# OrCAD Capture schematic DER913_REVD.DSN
size B; title: DER-913; rev: D
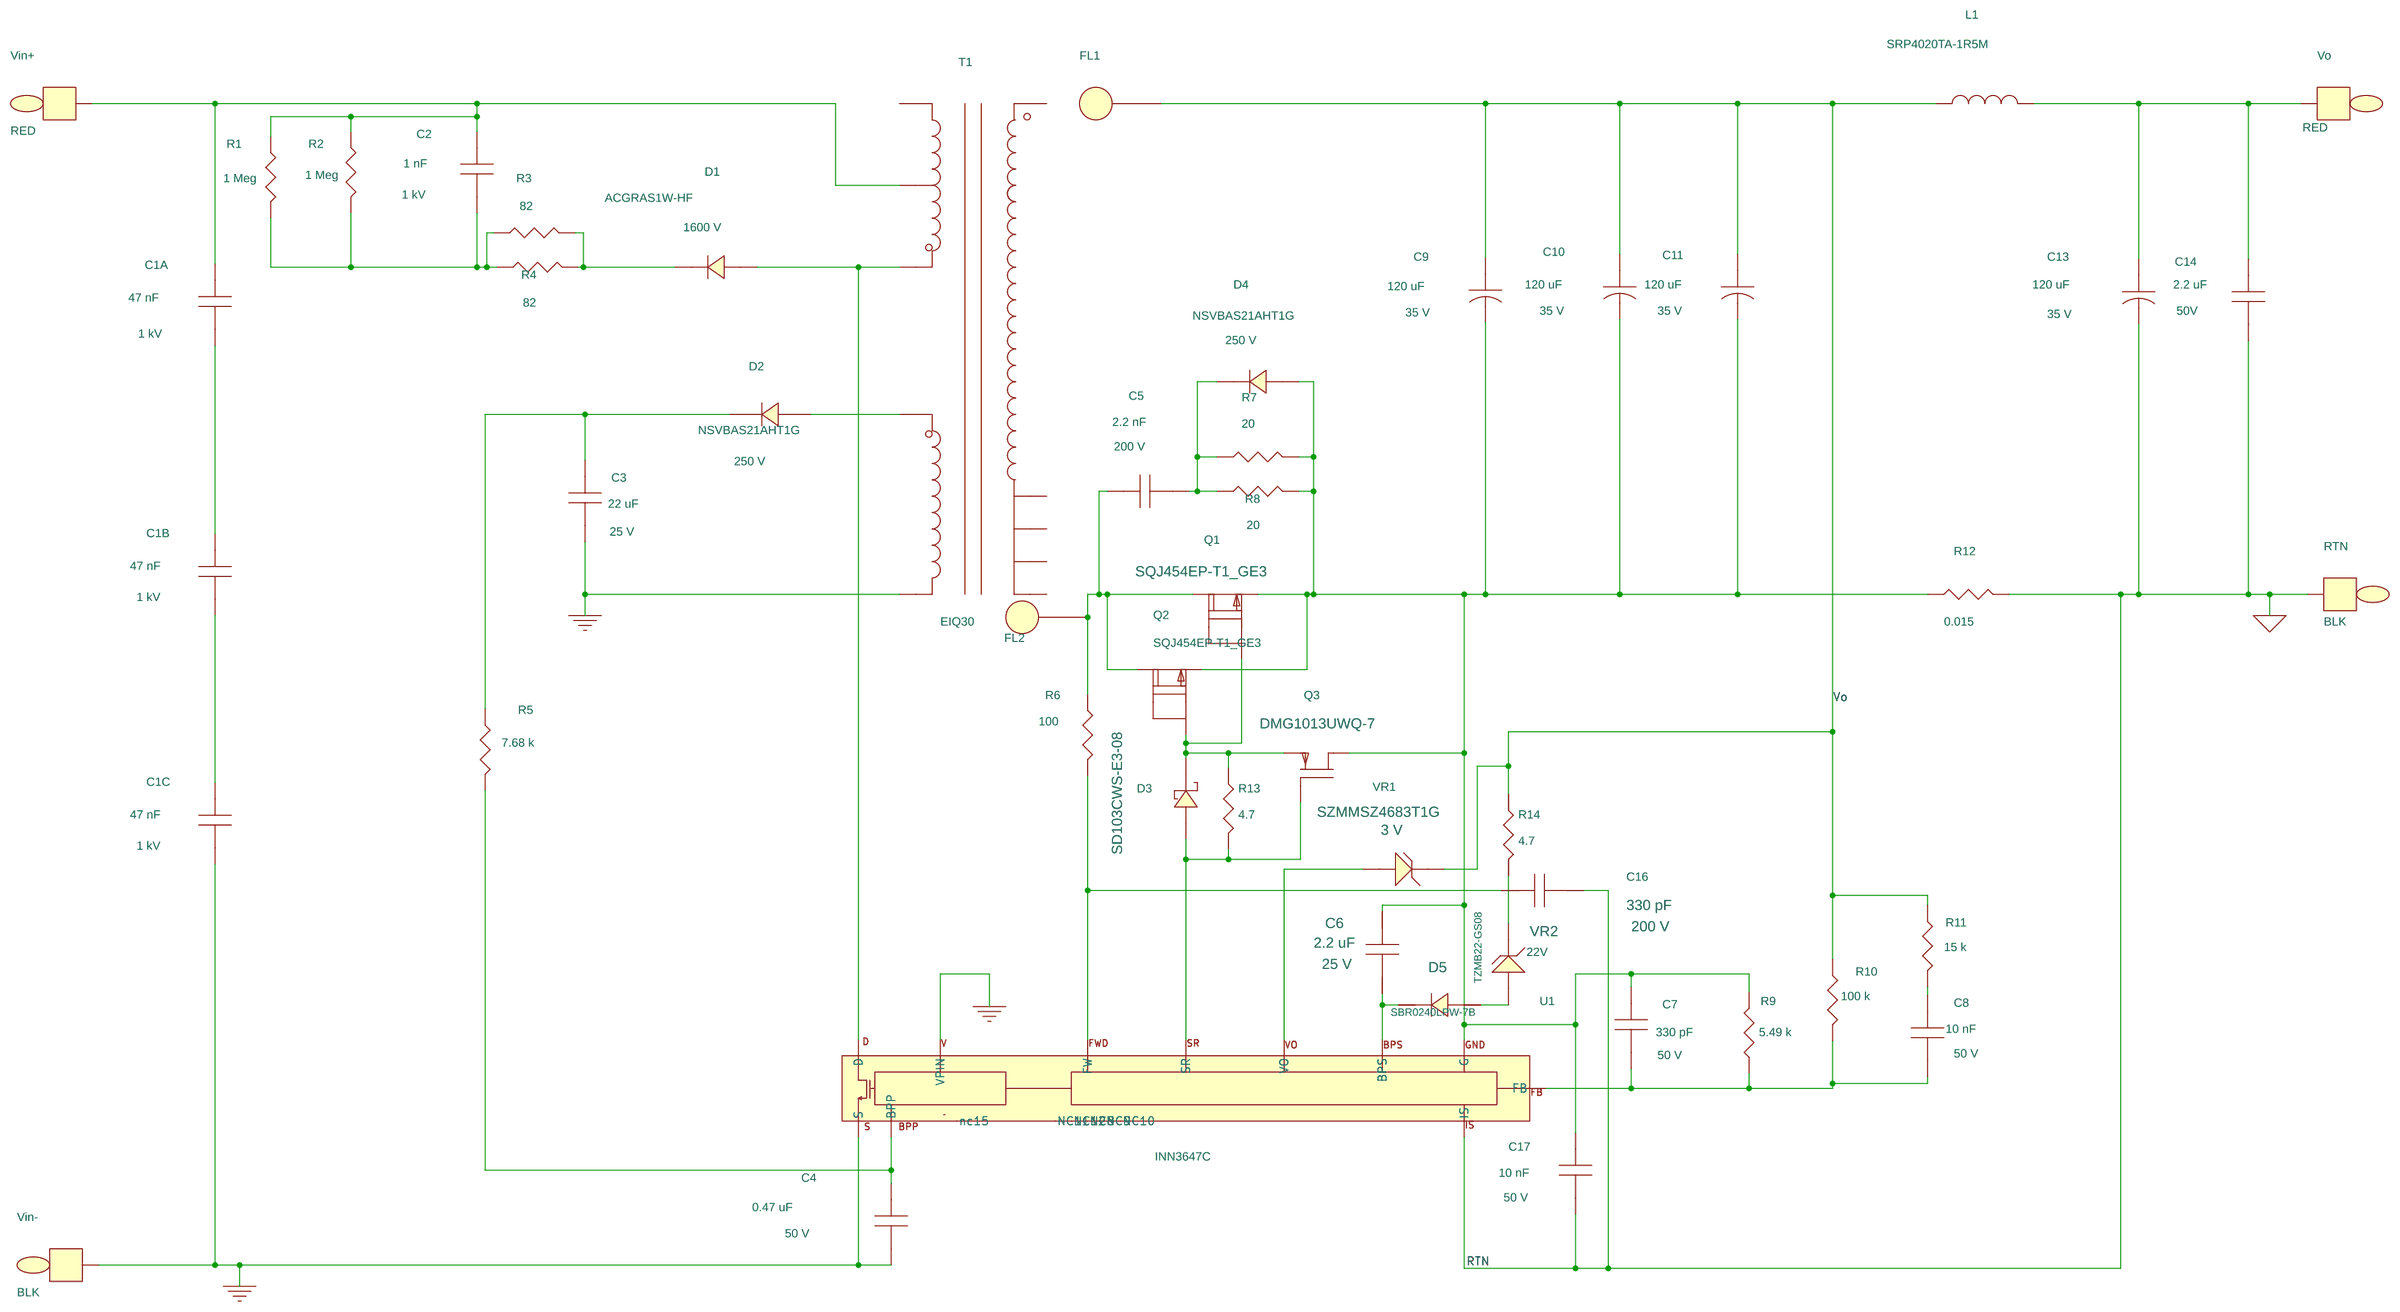
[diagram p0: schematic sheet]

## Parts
C1A  47 nF  [pismc1812]
C1B  47 nF  [pismc1812]
C1C  47 nF  [pismc1812]
C2  1 nF  [pismc1206]
C3  22 uF  [pismc0805]
C4  0.47 uF  [pismc0805]
C5  2.2 nF  [pismc0805]
C6  2.2 uF  [pismc0805]
C7  330 pF  [pismc0603]
C8  10 nF  [pismc0805]
C9  120 uF  [pismcUCC_F80alelect]
C10  120 uF  [pismcUCC_F80alelect]
C11  120 uF  [pismcUCC_F80alelect]
C13  120 uF  [pismcUCC_F80alelect]
C14  2.2 uF  [pismc1206]
C16  330 pF  [pismc0603]
C17  10 nF  [pismc0805]
D1  ACGRAS1W-HF  [pismdo214ac12]
D2  NSVBAS21AHT1G  [pismsod323]
D3  SD103CWS-E3-08  [pismsod323]
D4  NSVBAS21AHT1G  [pismsod323]
D5  SBR0240LPW-7B  [pi_sm_DFN1006-2]
FL1  Hole_70mils  [pi_hole_70mil]
FL2  Hole_70mils  [pi_hole_70mil]
L1  SRP4020TA-1R5M  [pi_sm_2-smd]
Q1  SQJ454EP-T1_GE3  [pismpqfn5x6bLa]
Q2  SQJ454EP-T1_GE3  [pismpqfn5x6bLa]
Q3  DMG1013UWQ-7  [pismsot323_GSD]
R1  1 Meg  [pismr1206]
R2  1 Meg  [pismr1206]
R3  82  [pismr1206]
R4  82  [pismr1206]
R5  7.68 k  [pismr0805]
R6  100  [pismr1206]
R7  20  [pismr1210]
R8  20  [pismr1210]
R9  5.49 k  [pismr0805]
R10  100 k  [pismr0805]
R11  15 k  [pismr0805]
R12  0.015  [pismr1206]
R13  4.7  [pismr0805]
R14  4.7  [pismr0805]
RTN  BLK  [pitpkeystone125x125]
T1  EIQ30  [pibobbineqi3010psmtslimcore]
U1  INN3647C  [pi_ic_insop_24D]
Vin+  RED  [pitpkeystone125x125]
Vin-  BLK  [pitpkeystone125x125]
Vo  RED  [pitpkeystone125x125]
VR1  SZMMSZ4683T1G  [pi_sm_sod-123_12]
VR2  TZMB22-GS08  [pi_sm_sod80C]

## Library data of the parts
C1A C1B C1C = CAP_NP: Disp_Voltage: 1 kV; Part Number: 20-09232-00; Voltage: 1000V
C2 = CAP_NP: Disp_Voltage: 1 kV; Part Number: 20-01391-00; Voltage: 1000 V
C3 = CAP_NP: Disp_Voltage: 25 V; Part Number: 20-01425-00; Voltage: 25 V
C4 = CAP_NP: Disp_Voltage: 50 V; Part Number: 20-09197-00; Voltage: 50 V
C5 = CAP_NP: Disp_Voltage: 200 V; Part Number: 20-09233-00; Voltage: 200 V
C6 = CAP_NP: Disp_Voltage: 25 V; Part Number: 20-01429-00; Voltage: 25 V
C7 = CAP_NP: ALT_SYMBOLS: pismc0603_1; Disp_Voltage: 50 V; FPLIST: pismc0603,pismc0603_1; Part Number: 20-09235-00; Voltage: 50 V
C8 C17 = CAP_NP: Disp_Voltage: 50 V; Part Number: 20-00965-00; Voltage: 50 V
C9-C11 C13 = CAP_POL: Disp_Voltage: 35 V; Part Number: 24-00068-00; Voltage: 35 V
C14 = CAP_NP: Disp_Voltage: 50V; Part Number: 20-09237-00; Voltage: 50 V
C16 = CAP_NP: Disp_Voltage: 200 V; Part Number: 20-01392-00; Voltage: 200 V
D1 = DIODE: Disp_Voltage: 1600 V; Part Number: 15-01637-00
D2 D4 = DIODE: ALT_SYMBOLS: pismsod323_1; Disp_Voltage: 250 V; FPLIST: pismsod323,pismsod323_1; Part Number: 15-01572-00
D3 = DIODE_SCHOTTKY: ALT_SYMBOLS: pismsod323_1; Disp_Voltage: 20 V; FPLIST: pismsod323,pismsod323_1; Part Number: 15-01600-00
D5 = DIODE: Part Number: 15-01636-00
FL1 FL2 = FlyingLead: Part Number: 35-00282-00
L1 = INDUCTOR: Part Number: 30-04112-00
Q1 Q2 = FET_N_SGD_123_4_5678: ALT_SYMBOLS: pismpqfn5x6bl; FPLIST: pismpqfn5x6bLa,pismpqfn5x6bl; Part Number: 50-00293-00
Q3 = FET_P_GSD: Part Number: 50-00313-00
R1 R2 = R: Disp_Power: 0.25 W; Disp_Tol: ±5%; Part Number: 05-06631-00
R3 R4 = R: Part Number: 05-01326-00
R5 = R: Disp_Tol: 1%; Part Number: 05-03390-00
R6 = R: Disp_Power: 1 W; Disp_Tol: 1%; Part Number: 05-06637-00
R7 R8 = R: Disp_Power: 0.5 W; Disp_Tol: 1%; Part Number: 05-06635-00
R9 = R: Disp_Tol: 1%; Part Number: 05-03377-00
R10 = R: Disp_Tol: 1%; Part Number: 05-00780-00
R11 = R: Part Number: 05-01547-00
R12 = R: Disp_Power: 1 W; Disp_Tol: 1%; Part Number: 05-06450-00
R13 R14 = R: Part Number: 05-01463-00
RTN Vin- = TESTPOINT: Part Number: 35-00042-00
T1 = BEQI30_10P_SMT_GENERIC_7: Part Number: 25-00887-00
U1 = Inno3AQ_P15_3: Part Number: 10-01289-00
Vin+ Vo = TESTPOINT: Part Number: 35-00043-00
VR1 = DIODE_ZENER: Disp_Voltage: 3 V; Part Number: 15-01616-00
VR2 = DIODE_ZENER: Disp_Voltage: 22V; Part Number: 15-01635-00

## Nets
GND: C1C.2 C3.2 C4.2 T1.4 U1.13(VPIN) U1.16(S) Vin-.1
GND SIGNAL: C13.2 C14.2 C16.2 C17.2 R12.2 RTN.1 U1.1(IS)
NC8: U1.8(NC8)
NC9: U1.9(NC9)
NC10: U1.10(NC10)
NC11: U1.11(NC11)
NC12: U1.12(NC12)
NC15: U1.15(nc15)
Vo: C9.1 C10.1 C11.1 FL1.1 L1.1 R10.1 R11.1 R14.1 VR1.1
N37213: C1A.1 C2.1 R1.1 R2.1 T1.2 Vin+.1
N37461: C5.2 D4.1 R7.1 R8.1
N37469: C6.1 C7.1 C9.2 C10.2 C11.2 C17.1 D4.2 Q1.1(S) Q2.1(S) Q3.2(S) R7.2 R8.2 R9.2 R12.1 U1.2(G)
N37817: C1A.2 C1B.1
N38055: C3.1 D2.1 R5.1
N38189: C4.1 R5.2 U1.14(BPP)
N51802: C13.1 C14.1 L1.2 Vo.1
N100534: C2.2 R1.2 R2.2 R3.1 R4.1
N100538: D1.1 R3.2 R4.2
N104424: C5.1 FL2.1 Q1.5(D) Q2.5(D) R6.1
N108749: C7.2 C8.2 R9.1 R10.2 U1.3(FB)
N109628: U1.6(VO) VR1.2
N109833: C8.1 R11.2
N12285951: D3.2(CATHODE) Q1.4(G) Q2.4(G) Q3.3(D) R13.1
N12285992: D3.1(ANODE) Q3.1(G) R13.2 U1.5(SR)
N12290249: D2.2 T1.5
N12293127: C16.1 R6.2 U1.7(FW)
N12298344: D1.2 T1.1 U1.24(D)
N12325575: C6.2 D5.1 U1.4(BPS)
N12326103: D5.2 VR2.2
N12333480: C1B.2 C1C.1
N12335935: R14.2 VR2.1

Not connected (* = marked no-connect by the designer): Q1 2(S2) 3(S3) 6(D6) 7(D7) 8(D8); Q2 2(S2) 3(S3) 6(D6) 7(D7) 8(D8); T1 3 6 7 8 9 10
